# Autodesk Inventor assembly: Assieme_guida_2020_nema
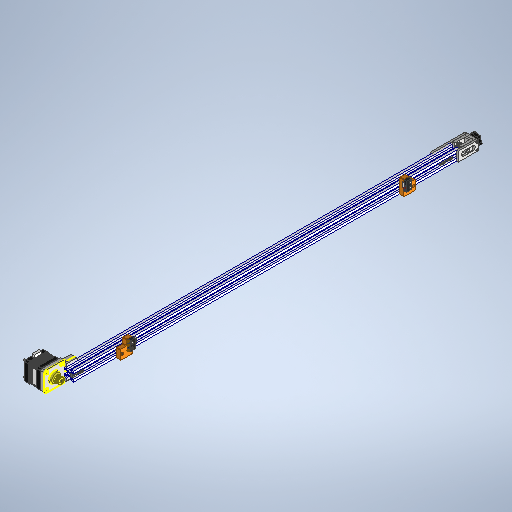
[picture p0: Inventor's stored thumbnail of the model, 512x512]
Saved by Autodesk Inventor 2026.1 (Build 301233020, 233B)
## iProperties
Created: 2026-01
Part Number: Assieme_guida_2020_nema
Document SubType Name: Assembly
Designer: hp
Sending System: Autodesk Inventor 2025
Preprocessor: ST-DEVELOPER v20
Title: Assieme_guida_2020_nema.stp
Author: R5800u
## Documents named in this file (18)
- C:\Users\hp\Documents\Inventor\DOM1_CartesianRobot\Assieme_guida_2020_nema.iam
- C:\Users\hp\Documents\Inventor\DOM1_CartesianRobot\2020.ipt
- C:\Users\hp\Documents\Inventor\DOM1_CartesianRobot\2020 Belt Tensioner G_K.iam
- C:\Users\hp\Documents\Inventor\DOM1_CartesianRobot\GT2_20T.ipt
- C:\Users\hp\Documents\Inventor\DOM1_CartesianRobot\NO-NC Limit Switch.ipt
- C:\Users\hp\Documents\Inventor\DOM1_CartesianRobot\blocco_sensore.ipt
- C:\Users\hp\Documents\Inventor\DOM1_CartesianRobot\blocco_sensore_MIR.ipt
- C:\Users\hp\Documents\Inventor\DOM1_CartesianRobot\NEMA 42SHDC3030Z.ipt
- C:\Users\hp\Documents\Inventor\DOM1_CartesianRobot\blocco_nema.ipt
- C:\Users\hp\Documents\Inventor\Content Center Files\R2026\en-US\ISO 4032(2)\ISO 4032 - M3 - ISO.ipt
- C:\Users\hp\Documents\Inventor\DOM1_CartesianRobot\2020 M3.ipt
- C:\Users\hp\Documents\Inventor\DOM1_CartesianRobot\2020 M4 (1).ipt
- C:\Users\hp\Documents\Inventor\Content Center Files\R2026\en-US\ISO 4017(1)\ISO 4017 - M2 x 16 - ISO.ipt
- C:\Users\hp\Documents\Inventor\Content Center Files\R2026\en-US\ISO 4035(2)\ISO 4035 - M2 - ISO.ipt
- C:\Users\hp\Documents\Inventor\Content Center Files\R2026\en-US\ISO 4017(1)\ISO 4017 - M4 x 25 - ISO.ipt
- C:\Users\hp\Documents\Inventor\Content Center Files\R2021\en-US\ANSI B18.3.1M(2)\ANSI B18.3.1M - M3x0.5 x 45(6).ipt
- C:\Users\hp\Documents\Inventor\Content Center Files\R2026\en-US\ISO 4762(2)\ISO 4762 - M4 x 25ISO.ipt
- C:\Users\hp\Documents\Inventor\Content Center Files\R2026\en-US\ISO 4762(2)\ISO 4762 - M3 x 25ISO.ipt
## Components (39 placed, 17 different names)
1. 2020:1
2. 2020 Belt Tensioner G_K:1 [sub-assembly]
3. GT2_20T:1 — Rigid:1
4. NO-NC Limit Switch:1
5. NO-NC Limit Switch:2
6. blocco_sensore:1 — Mate:6, Mate:9, Mate:10, Mate:11, Mate:57, Mate:59, Mate:106, Flush:2, Mate:113, Mate:114, Mate:115, Mate:116
7. blocco_sensore_MIR:1
8. NEMA 42SHDC3030Z:1 — Mate:1, Mate:2, Mate:3, Rigid:1, Mate:99, Mate:101, Mate:103, Mate:105
9. blocco_nema:1
10. 2020 M3:1 — Mate:63, Angle:3, Mate:118
11. 2020 M4 (1):1 — Mate:36, Angle:2, Mate:45, Mate:112
12. 2020 M3:2 — Mate:62, Angle:4, Mate:117
13. 2020 M4 (1):2 — Mate:44, Angle:1, Mate:111
14. ISO 4017 M2 x 16:1 — Mate:52, Mate:53
15. ISO 4035 M2:1 — Mate:56, Mate:57
16. ISO 4017 M2 x 16:2 — Mate:54, Mate:55
17. ISO 4035 M2:2 — Mate:58, Mate:59
18. ISO 4017 M4 x 25:1 — Mate:65, Mate:66, Mate:82
19. ISO 4017 M4 x 25:2 — Mate:67, Mate:68, Mate:81
20. ISO 4017 M2 x 16:3 — Mate:73, Mate:74
21. ISO 4035 M2:3 — Mate:77, Mate:78
22. ISO 4017 M2 x 16:4 — Mate:75, Mate:76
23. ISO 4035 M2:4 — Mate:79, Mate:80
24. 2020 M3:3 — Mate:88, Angle:9
25. 2020 M4 (1):3 — Mate:81, Mate:83, Angle:7
26. 2020 M4 (1):4 — Mate:82, Mate:84, Angle:6
27. 2020 M3:4 — Mate:89, Angle:8
28. Drilled Broached Hexagon Socket Head Cap Screw - 2 Holes - Metric M3x0.5 x 45:1 — Mate:90, Mate:91
29. ISO 4032 M3:1 — Mate:98, Mate:99
30. Drilled Broached Hexagon Socket Head Cap Screw - 2 Holes - Metric M3x0.5 x 45:2 — Mate:92, Mate:93
31. Drilled Broached Hexagon Socket Head Cap Screw - 2 Holes - Metric M3x0.5 x 45:3 — Mate:94, Mate:95
32. Drilled Broached Hexagon Socket Head Cap Screw - 2 Holes - Metric M3x0.5 x 45:4 — Mate:96, Mate:97
33. ISO 4032 M3:2 — Mate:100, Mate:101
34. ISO 4032 M3:3 — Mate:102, Mate:103
35. ISO 4032 M3:4 — Mate:104, Mate:105
36. ISO 4762 M4 x 25:1 — Mate:107, Mate:108, Mate:112
37. ISO 4762 M4 x 25:2 — Mate:109, Mate:110, Mate:111
38. ISO 4762 M3 x 25:1 — Mate:113, Mate:114, Mate:117
39. ISO 4762 M3 x 25:2 — Mate:115, Mate:116, Mate:118
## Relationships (77: Mate 67, Angle 8, WeldJoint 1, Flush 1)
- Mate:1: NEMA 42SHDC3030Z:1
- Mate:2: NEMA 42SHDC3030Z:1
- Mate:3: NEMA 42SHDC3030Z:1
- Rigid:1 [WeldJoint]: GT2_20T:1 ↔ NEMA 42SHDC3030Z:1
- Mate:6: blocco_sensore:1
- Mate:9: blocco_sensore:1
- Mate:10: blocco_sensore:1
- Mate:11: blocco_sensore:1
- Mate:36: 2020 M4 (1):1
- Mate:44: 2020 M4 (1):2
- Angle:1: 2020 M4 (1):2
- Angle:2: 2020 M4 (1):1
- Mate:45: 2020 M4 (1):1
- Mate:52: ISO 4017 M2 x 16:1
- Mate:53: ISO 4017 M2 x 16:1
- Mate:54: ISO 4017 M2 x 16:2
- Mate:55: ISO 4017 M2 x 16:2
- Mate:56: ISO 4035 M2:1
- Mate:57: blocco_sensore:1 ↔ ISO 4035 M2:1
- Mate:58: ISO 4035 M2:2
- Mate:59: blocco_sensore:1 ↔ ISO 4035 M2:2
- Mate:62: 2020 M3:2
- Mate:63: 2020 M3:1
- Angle:3: 2020 M3:1
- Angle:4: 2020 M3:2
- Mate:65: ISO 4017 M4 x 25:1
- Mate:66: ISO 4017 M4 x 25:1
- Mate:67: ISO 4017 M4 x 25:2
- Mate:68: ISO 4017 M4 x 25:2
- Mate:73: ISO 4017 M2 x 16:3
- Mate:74: ISO 4017 M2 x 16:3
- Mate:75: ISO 4017 M2 x 16:4
- Mate:76: ISO 4017 M2 x 16:4
- Mate:77: ISO 4035 M2:3
- Mate:78: ISO 4035 M2:3
- Mate:79: ISO 4035 M2:4
- Mate:80: ISO 4035 M2:4
- Mate:81: ISO 4017 M4 x 25:2 ↔ 2020 M4 (1):3
- Mate:82: ISO 4017 M4 x 25:1 ↔ 2020 M4 (1):4
- Mate:83: 2020 M4 (1):3
- Mate:84: 2020 M4 (1):4
- Angle:6: 2020 M4 (1):4
- Angle:7: 2020 M4 (1):3
- Mate:88: 2020 M3:3
- Mate:89: 2020 M3:4
- Angle:8: 2020 M3:4
- Angle:9: 2020 M3:3
- Mate:90: Drilled Broached Hexagon Socket Head Cap Screw - 2 Holes - Metric M3x0.5 x 45:1
- Mate:91: Drilled Broached Hexagon Socket Head Cap Screw - 2 Holes - Metric M3x0.5 x 45:1
- Mate:92: Drilled Broached Hexagon Socket Head Cap Screw - 2 Holes - Metric M3x0.5 x 45:2
- Mate:93: Drilled Broached Hexagon Socket Head Cap Screw - 2 Holes - Metric M3x0.5 x 45:2
- Mate:94: Drilled Broached Hexagon Socket Head Cap Screw - 2 Holes - Metric M3x0.5 x 45:3
- Mate:95: Drilled Broached Hexagon Socket Head Cap Screw - 2 Holes - Metric M3x0.5 x 45:3
- Mate:96: Drilled Broached Hexagon Socket Head Cap Screw - 2 Holes - Metric M3x0.5 x 45:4
- Mate:97: Drilled Broached Hexagon Socket Head Cap Screw - 2 Holes - Metric M3x0.5 x 45:4
- Mate:98: ISO 4032 M3:1
- Mate:99: NEMA 42SHDC3030Z:1 ↔ ISO 4032 M3:1
- Mate:100: ISO 4032 M3:2
- Mate:101: NEMA 42SHDC3030Z:1 ↔ ISO 4032 M3:2
- Mate:102: ISO 4032 M3:3
- Mate:103: NEMA 42SHDC3030Z:1 ↔ ISO 4032 M3:3
- Mate:104: ISO 4032 M3:4
- Mate:105: NEMA 42SHDC3030Z:1 ↔ ISO 4032 M3:4
- Mate:106: blocco_sensore:1
- Flush:2: blocco_sensore:1
- Mate:107: ISO 4762 M4 x 25:1
- Mate:108: ISO 4762 M4 x 25:1
- Mate:109: ISO 4762 M4 x 25:2
- Mate:110: ISO 4762 M4 x 25:2
- Mate:111: 2020 M4 (1):2 ↔ ISO 4762 M4 x 25:2
- Mate:112: 2020 M4 (1):1 ↔ ISO 4762 M4 x 25:1
- Mate:113: blocco_sensore:1 ↔ ISO 4762 M3 x 25:1
- Mate:114: blocco_sensore:1 ↔ ISO 4762 M3 x 25:1
- Mate:115: blocco_sensore:1 ↔ ISO 4762 M3 x 25:2
- Mate:116: blocco_sensore:1 ↔ ISO 4762 M3 x 25:2
- Mate:117: 2020 M3:2 ↔ ISO 4762 M3 x 25:1
- Mate:118: 2020 M3:1 ↔ ISO 4762 M3 x 25:2
